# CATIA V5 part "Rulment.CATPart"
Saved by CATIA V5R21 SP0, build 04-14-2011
Part number: Rulment
Bounding box of the stored display mesh (mm): x -27.5 to 27.5, y -27.5 to 27.5, z 84 to 109
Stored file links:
  C:\Users\MIRCEA\Desktop\PRRO\CATIAV5\Rulment.CATPart
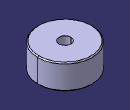
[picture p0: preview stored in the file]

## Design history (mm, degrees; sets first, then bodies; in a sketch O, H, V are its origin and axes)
Body1 (main body)
  Plane1: type Offset, RefPlane xy-plane, Offset 109
  Sketch1 on Plane1, origin (0, 0, 109), H (1, 0, 0), V (0, 1, 0)
    circle A1 centre (0, 0) radius 6
    circle A2 centre (0, 0) radius 27.5
    radius A1 = 6
    radius A2 = 27.5
  Pad1: profile Sketch1, direction (0, 0, -1), length 25
  Chamfer1: length 1, angle 45, on end face of Pad1; edge [face of Pad1 from Sketch1.A2 | start face of Pad1]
